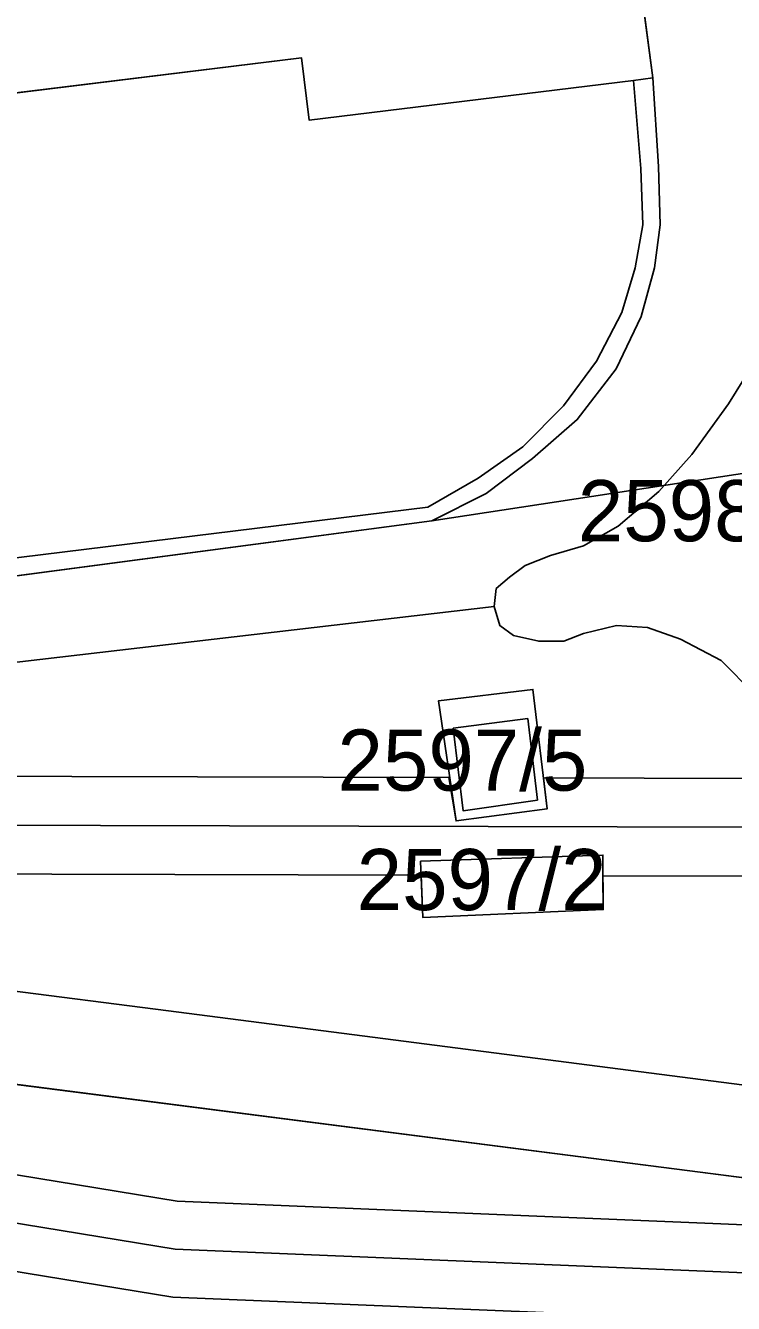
# Model space of a CAD drawing. Extents: x -263423 to -261326, y -1240067 to -1237864.
# Drawn here: x -263213.92 to -263190.74, y -1239995.28 to -1239953.46 of the extents above; entities that cross this region are included whole.
import ezdxf

# ---------------------------------------------------------------- set-up
doc = ezdxf.new("R2010")
doc.units = 0
for name, color, linetype in [('body_kn', 7, 'Continuous'), ('kladpar_druhypozemkov', 7, 'Continuous'), ('kladpar_hranice', 7, 'Continuous'), ('kladpar_parcelnecisla', 7, 'Continuous'), ('kladpar_plochy', 7, 'Continuous'), ('linie', 7, 'Continuous'), ('tarchy_linie', 7, 'Continuous'), ('zappar_hrandruhpozemk', 7, 'Continuous')]:
    doc.layers.add(name, color=color, linetype=linetype)

msp = doc.modelspace()

# ---------------------------------------------------------------- linework, layer by layer
at = {"layer": 'body_kn'}
for p, q in [((-263204.89, -1239954.52), (-263204.89, -1239954.52)), ((-263193.38, -1239955.18), (-263193.38, -1239955.18)), ((-263193.38, -1239955.18), (-263193.38, -1239955.18)), ((-263194.02, -1239955.26), (-263194.02, -1239955.26)), ((-263204.64, -1239956.56), (-263204.64, -1239956.56)), ((-263193.78, -1239958.14), (-263193.78, -1239958.14)), ((-263193.2, -1239958.08), (-263193.2, -1239958.08)), ((-263193.71, -1239959.99), (-263193.71, -1239959.99)), ((-263193.14, -1239959.99), (-263193.14, -1239959.99)), ((-263193.96, -1239961.39), (-263193.96, -1239961.39)), ((-263193.33, -1239961.39), (-263193.33, -1239961.39)), ((-263194.4, -1239962.85), (-263194.4, -1239962.85)), ((-263193.77, -1239962.98), (-263193.77, -1239962.98)), ((-263195.23, -1239964.45), (-263195.23, -1239964.45)), ((-263194.59, -1239964.7), (-263194.59, -1239964.7)), ((-263196.31, -1239965.91), (-263196.31, -1239965.91)), ((-263196.31, -1239965.91), (-263196.31, -1239965.91)), ((-263190.91, -1239965.84), (-263190.91, -1239965.84)), ((-263195.86, -1239966.36), (-263195.86, -1239966.36)), ((-263197.64, -1239967.25), (-263197.64, -1239967.25)), ((-263197.32, -1239967.63), (-263197.32, -1239967.63)), ((-263192.11, -1239967.5), (-263192.11, -1239967.5)), ((-263199.1, -1239968.27), (-263199.1, -1239968.27)), ((-263198.84, -1239968.78), (-263198.84, -1239968.78)), ((-263193.19, -1239968.71), (-263193.19, -1239968.71)), ((-263200.75, -1239969.22), (-263200.75, -1239969.22)), ((-263200.62, -1239969.67), (-263200.62, -1239969.67)), ((-263194.52, -1239969.85), (-263194.52, -1239969.85)), ((-263195.66, -1239970.49), (-263195.66, -1239970.49)), ((-263197.57, -1239971.13), (-263197.57, -1239971.13)), ((-263196.74, -1239970.81), (-263196.74, -1239970.81)), ((-263198.08, -1239971.51), (-263198.08, -1239971.51)), ((-263198.52, -1239971.89), (-263198.52, -1239971.89)), ((-263198.58, -1239972.47), (-263198.58, -1239972.47)), ((-263198.58, -1239972.47), (-263198.58, -1239972.47)), ((-263198.39, -1239973.1), (-263198.39, -1239973.1)), ((-263194.58, -1239973.1), (-263194.58, -1239973.1)), ((-263193.56, -1239973.16), (-263193.56, -1239973.16)), ((-263197.95, -1239973.42), (-263197.95, -1239973.42)), ((-263197.12, -1239973.61), (-263197.12, -1239973.61)), ((-263196.3, -1239973.61), (-263196.3, -1239973.61)), ((-263195.66, -1239973.36), (-263195.66, -1239973.36)), ((-263192.48, -1239973.54), (-263192.48, -1239973.54)), ((-263191.15, -1239974.24), (-263191.15, -1239974.24)), ((-263197.31, -1239975.19), (-263197.31, -1239975.19)), ((-263197.31, -1239975.19), (-263197.31, -1239975.19)), ((-263200.4, -1239975.56), (-263200.4, -1239975.56)), ((-263197.48, -1239976.14), (-263197.48, -1239976.14)), ((-263199.92, -1239976.46), (-263199.92, -1239976.46)), ((-263200.07, -1239978.07), (-263200.07, -1239978.07)), ((-263196.97, -1239978.08), (-263196.97, -1239978.08)), ((-263197.16, -1239978.81), (-263197.16, -1239978.81)), ((-263197.16, -1239978.81), (-263197.16, -1239978.81)), ((-263199.83, -1239979.49), (-263199.83, -1239979.49)), ((-263199.6, -1239979.16), (-263199.6, -1239979.16)), ((-263196.85, -1239979.1), (-263196.85, -1239979.1)), ((-263195.02, -1239980.61), (-263195.02, -1239980.61)), ((-263195.02, -1239980.61), (-263195.02, -1239980.61)), ((-263200.99, -1239980.81), (-263200.99, -1239980.81)), ((-263200.97, -1239981.27), (-263200.97, -1239981.27)), ((-263195.02, -1239981.29), (-263195.02, -1239981.29)), ((-263195.01, -1239982.39), (-263195.01, -1239982.39)), ((-263200.92, -1239982.65), (-263200.92, -1239982.65)), ((-263209.24, -1239985.71), (-263209.24, -1239985.71)), ((-263191.83, -1239990.98), (-263191.83, -1239990.98)), ((-263208.96, -1239991.93), (-263208.96, -1239991.93)), ((-263209.03, -1239993.5), (-263209.03, -1239993.5)), ((-263209.1, -1239995.07), (-263209.1, -1239995.07))]:
    msp.add_line(p, q, dxfattribs=at)
at = {"layer": 'kladpar_druhypozemkov'}
for p, q in [((-263198.57, -1239976.7), (-263198.57, -1239976.7)), ((-263197.79, -1239981.08), (-263197.79, -1239981.08))]:
    msp.add_line(p, q, dxfattribs=at)
at = {"layer": 'kladpar_hranice'}
for points in [[(-263190.22, -1239907.6), (-263184.32, -1239965.74), (-263184.15, -1239967.16), (-263183.88, -1239969.44), (-263183.42, -1239973.72), (-263181.29, -1239992.35), (-263191.83, -1239990.98)], [(-263193.38, -1239955.18), (-263194.02, -1239955.26), (-263204.64, -1239956.56), (-263204.89, -1239954.52), (-263223.86, -1239956.85), (-263224.6, -1239956.94), (-263224.34, -1239959.03), (-263227.63, -1239959.44), (-263227.89, -1239957.36), (-263228.32, -1239957.41), (-263236.25, -1239958.41), (-263236.13, -1239959.38), (-263249.35, -1239961.02), (-263249.47, -1239960.06), (-263283.64, -1239963.85), (-263283.42, -1239965.86), (-263285.6, -1239966.19), (-263285.21, -1239968.21), (-263288.47, -1239970.5), (-263292.24, -1239969.54), (-263292.7, -1239967.53), (-263294.69, -1239968.53), (-263301.23, -1239938.71)], [(-263269.02, -1239977.22), (-263266.8, -1239977.22), (-263226.02, -1239972.99), (-263221.83, -1239972.48), (-263200.62, -1239969.67), (-263198.84, -1239968.78), (-263197.32, -1239967.63), (-263195.86, -1239966.36), (-263194.59, -1239964.7), (-263193.77, -1239962.98), (-263193.33, -1239961.39), (-263193.14, -1239959.99), (-263193.2, -1239958.08), (-263193.38, -1239955.18), (-263195.14, -1239941.99)], [(-263195.14, -1239941.99), (-263193.38, -1239955.18)], [(-263223.86, -1239956.85), (-263204.89, -1239954.52), (-263204.64, -1239956.56), (-263194.02, -1239955.26), (-263193.38, -1239955.18), (-263193.2, -1239958.08), (-263193.14, -1239959.99), (-263193.33, -1239961.39), (-263193.77, -1239962.98), (-263194.59, -1239964.7), (-263195.86, -1239966.36), (-263197.32, -1239967.63), (-263198.84, -1239968.78), (-263200.62, -1239969.67), (-263221.83, -1239972.48)], [(-263197.31, -1239975.19), (-263196.85, -1239979.1), (-263199.83, -1239979.49), (-263200.4, -1239975.56), (-263197.31, -1239975.19)], [(-263196.85, -1239979.1), (-263197.31, -1239975.19), (-263200.4, -1239975.56), (-263199.83, -1239979.49), (-263196.85, -1239979.1)], [(-263271.44, -1239977.73), (-263248.75, -1239983.7), (-263191.83, -1239990.98), (-263181.29, -1239992.35), (-263173.78, -1239993.33), (-263172.19, -1239993.39), (-263170.67, -1239993.32), (-263169.27, -1239993.07), (-263160.43, -1239993.94), (-263153.75, -1239994.6)], [(-263191.83, -1239990.98), (-263248.75, -1239983.7), (-263271.44, -1239977.73)], [(-263195.02, -1239980.61), (-263195.01, -1239982.39), (-263200.92, -1239982.65), (-263200.99, -1239980.81), (-263195.02, -1239980.61)], [(-263195.01, -1239982.39), (-263195.02, -1239980.61), (-263200.99, -1239980.81), (-263200.92, -1239982.65), (-263195.01, -1239982.39)]]:
    msp.add_lwpolyline(points, dxfattribs=at)
at = {"layer": 'kladpar_plochy'}
for p, q in [((-263195.14, -1239941.99), (-263193.38, -1239955.18)), ((-263193.38, -1239955.18), (-263195.14, -1239941.99)), ((-263204.89, -1239954.52), (-263223.86, -1239956.85)), ((-263204.64, -1239956.56), (-263204.89, -1239954.52)), ((-263193.38, -1239955.18), (-263194.02, -1239955.26)), ((-263193.2, -1239958.08), (-263193.38, -1239955.18)), ((-263194.02, -1239955.26), (-263204.64, -1239956.56)), ((-263193.14, -1239959.99), (-263193.2, -1239958.08)), ((-263193.33, -1239961.39), (-263193.14, -1239959.99)), ((-263193.77, -1239962.98), (-263193.33, -1239961.39)), ((-263194.59, -1239964.7), (-263193.77, -1239962.98)), ((-263195.86, -1239966.36), (-263194.59, -1239964.7)), ((-263197.32, -1239967.63), (-263195.86, -1239966.36)), ((-263198.84, -1239968.78), (-263197.32, -1239967.63)), ((-263200.62, -1239969.67), (-263198.84, -1239968.78)), ((-263221.83, -1239972.48), (-263200.62, -1239969.67)), ((-263197.31, -1239975.19), (-263200.4, -1239975.56)), ((-263196.85, -1239979.1), (-263197.31, -1239975.19)), ((-263200.4, -1239975.56), (-263199.83, -1239979.49)), ((-263199.83, -1239979.49), (-263196.85, -1239979.1)), ((-263195.02, -1239980.61), (-263200.99, -1239980.81)), ((-263195.01, -1239982.39), (-263195.02, -1239980.61)), ((-263200.99, -1239980.81), (-263200.92, -1239982.65)), ((-263200.92, -1239982.65), (-263195.01, -1239982.39)), ((-263248.75, -1239983.7), (-263191.83, -1239990.98)), ((-263191.83, -1239990.98), (-263248.75, -1239983.7)), ((-263191.83, -1239990.98), (-263181.29, -1239992.35)), ((-263181.29, -1239992.35), (-263191.83, -1239990.98))]:
    msp.add_line(p, q, dxfattribs=at)
msp.add_lwpolyline([(-263223.86, -1239956.85), (-263204.89, -1239954.52), (-263204.64, -1239956.56), (-263194.02, -1239955.26), (-263193.38, -1239955.18), (-263193.2, -1239958.08), (-263193.14, -1239959.99), (-263193.33, -1239961.39), (-263193.77, -1239962.98), (-263194.59, -1239964.7), (-263195.86, -1239966.36), (-263197.32, -1239967.63), (-263198.84, -1239968.78), (-263200.62, -1239969.67), (-263221.83, -1239972.48)], dxfattribs=at)
for points in [[(-263197.31, -1239975.19), (-263196.85, -1239979.1), (-263199.83, -1239979.49), (-263200.4, -1239975.56)], [(-263195.02, -1239980.61), (-263195.01, -1239982.39), (-263200.92, -1239982.65), (-263200.99, -1239980.81)]]:
    msp.add_lwpolyline(points, close=True, dxfattribs=at)
at = {"layer": 'linie'}
msp.add_lwpolyline([(-263142.39, -1239960.79), (-263161.9, -1239963.77), (-263165.62, -1239964.33), (-263167.57, -1239964.63), (-263171.14, -1239965.17), (-263175.09, -1239965.78), (-263178.63, -1239966.32), (-263184.15, -1239967.16), (-263200.62, -1239969.67), (-263221.83, -1239972.48), (-263226.02, -1239972.99), (-263271.44, -1239977.73), (-263294.57, -1239975.32)], dxfattribs=at)
at = {"layer": 'tarchy_linie'}
for points in [[(-263294.6, -1239973.59), (-263291.63, -1239974.47), (-263273.28, -1239975.85), (-263273.09, -1239975.95), (-263270.87, -1239976.78), (-263269.02, -1239977.22), (-263266.8, -1239977.22), (-263261.88, -1239976.71), (-263245.34, -1239977.95), (-263200.07, -1239978.07), (-263199.83, -1239979.49), (-263196.85, -1239979.1), (-263196.97, -1239978.08), (-263190.37, -1239978.1), (-263157.01, -1239977.05)], [(-263155.27, -1239995.7), (-263172.95, -1239996.57), (-263209.1, -1239995.07), (-263262.48, -1239986.35), (-263291.97, -1239977.65), (-263294.53, -1239977.46), (-263294.56, -1239975.85), (-263294.57, -1239975.32), (-263294.57, -1239975.24), (-263294.58, -1239974.58), (-263294.6, -1239973.59)], [(-263147.76, -1239993.75), (-263173.03, -1239995), (-263209.03, -1239993.5), (-263262.23, -1239984.8), (-263294.57, -1239975.24)], [(-263150.15, -1239978.44), (-263190.32, -1239979.7), (-263245.34, -1239979.55), (-263294.56, -1239975.85)], [(-263190.27, -1239981.3), (-263156.71, -1239980.25), (-263155.56, -1239992.56), (-263173.11, -1239993.43), (-263208.96, -1239991.93), (-263261.98, -1239983.25), (-263277.11, -1239978.77), (-263245.34, -1239981.15), (-263200.97, -1239981.27), (-263200.92, -1239982.65), (-263195.01, -1239982.39), (-263195.02, -1239981.29), (-263190.27, -1239981.3)]]:
    msp.add_lwpolyline(points, dxfattribs=at)
at = {"layer": 'zappar_hrandruhpozemk'}
for p, q in [((-263199.1, -1239968.27), (-263197.64, -1239967.25)), ((-263199.92, -1239976.46), (-263197.48, -1239976.14)), ((-263197.48, -1239976.14), (-263197.16, -1239978.81)), ((-263244.05, -1239981.22), (-263209.24, -1239985.71)), ((-263209.24, -1239985.71), (-263187.13, -1239988.56))]:
    msp.add_line(p, q, dxfattribs=at)
for points in [[(-263190.07, -1239975.33), (-263191.15, -1239974.24), (-263192.48, -1239973.54), (-263193.56, -1239973.16), (-263194.58, -1239973.1), (-263195.66, -1239973.36), (-263196.3, -1239973.61), (-263197.12, -1239973.61), (-263197.95, -1239973.42), (-263198.39, -1239973.1), (-263198.58, -1239972.47), (-263198.52, -1239971.89), (-263198.08, -1239971.51), (-263197.57, -1239971.13), (-263196.74, -1239970.81), (-263195.66, -1239970.49), (-263194.52, -1239969.85), (-263193.19, -1239968.71), (-263192.11, -1239967.5), (-263190.91, -1239965.84), (-263189.96, -1239964.32), (-263189.13, -1239962.34), (-263189.01, -1239960.5), (-263190.68, -1239943.95)], [(-263197.64, -1239967.25), (-263196.31, -1239965.91), (-263195.23, -1239964.45), (-263194.4, -1239962.85), (-263193.96, -1239961.39), (-263193.71, -1239959.99), (-263193.78, -1239958.14), (-263194.02, -1239955.26)], [(-263196.31, -1239965.91), (-263195.23, -1239964.45), (-263194.4, -1239962.85)], [(-263196.31, -1239965.91), (-263195.23, -1239964.45), (-263194.4, -1239962.85)], [(-263222.47, -1239970.38), (-263222.15, -1239971.08), (-263221.77, -1239971.46), (-263221.07, -1239971.72), (-263200.75, -1239969.22), (-263199.1, -1239968.27)], [(-263198.58, -1239972.47), (-263244.06, -1239977.78), (-263244.05, -1239981.22)], [(-263197.16, -1239978.81), (-263199.6, -1239979.16), (-263199.92, -1239976.46)]]:
    msp.add_lwpolyline(points, dxfattribs=at)

# ---------------------------------------------------------------- texts
at = {"layer": 'kladpar_parcelnecisla'}
for s, p in [('2598/26', (-263195.841, -1239970.34)), ('2597/5', (-263203.71, -1239978.5)), ('2597/2', (-263203.081, -1239982.41))]:
    msp.add_text(s, height=2, dxfattribs=at).set_placement(p)

doc.saveas('drawing.dxf')
